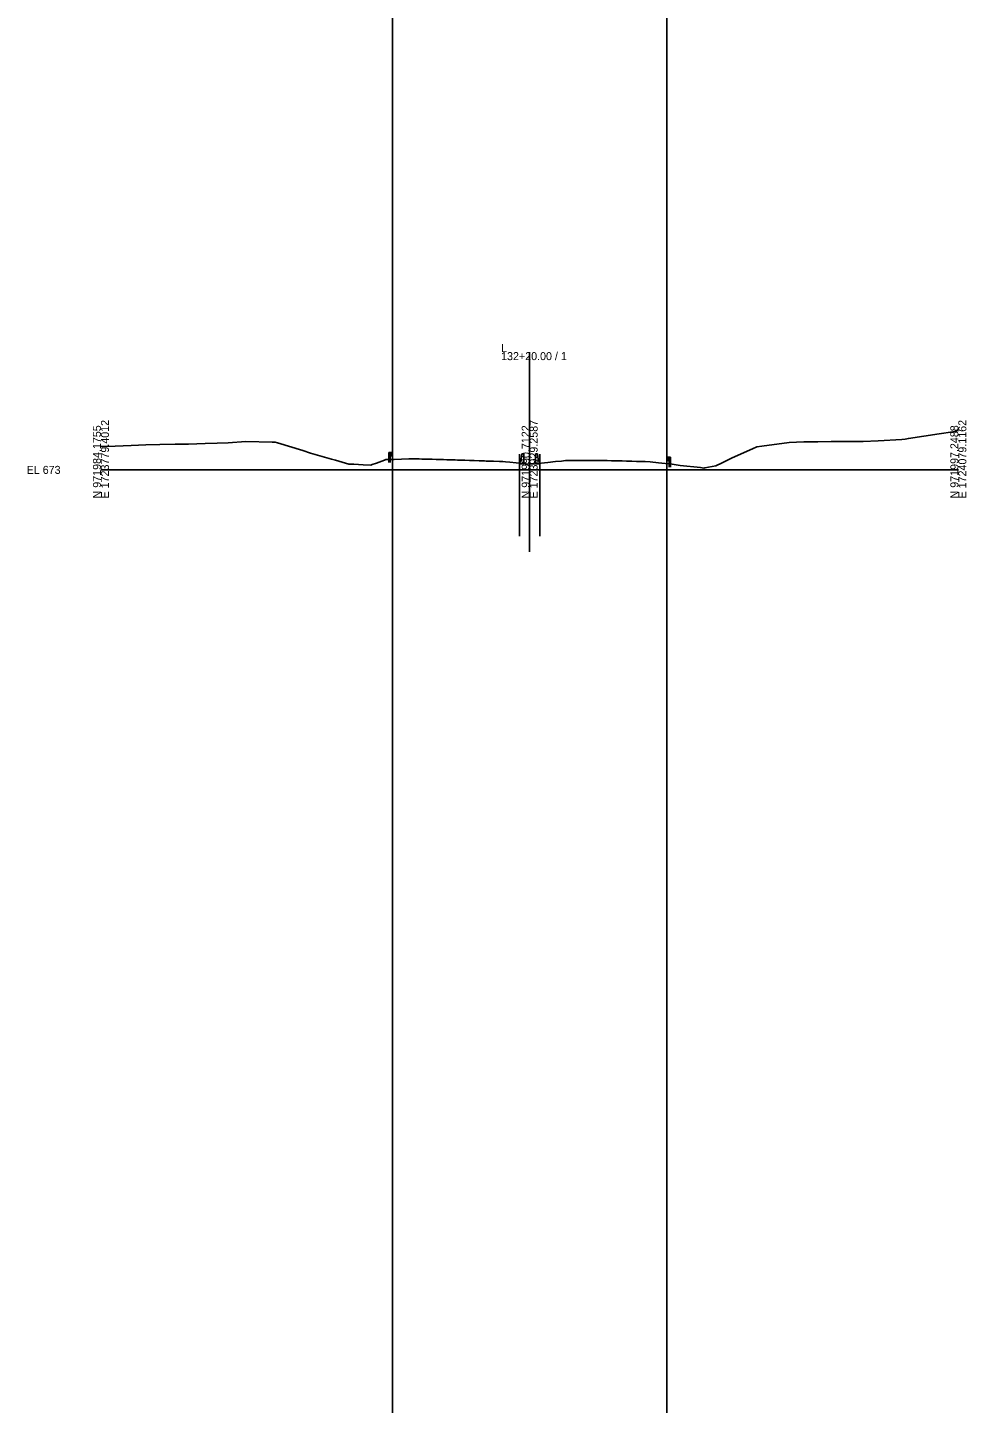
# Model space of a CAD drawing. Extents: x -26 to 303, y -29 to 15026.
# Drawn here: x -25.7 to 302.8, y 11173.3 to 11654.8 of the extents above; entities that cross this region are included whole.
import ezdxf

# ---------------------------------------------------------------- set-up
doc = ezdxf.new("R2010")
doc.units = 0
for name, color, linetype in [('Exist Cross Section Cell', 7, 'Continuous'), ('Exist XS Center Line Elevation Label', 7, 'Continuous'), ('Exist XS Ground Line', 7, 'Continuous'), ('Scratch_Level_0', 7, 'Continuous'), ('Typical Guardrail CELL', 7, 'Continuous'), ('Typical Median Barrier CELL', 7, 'Continuous')]:
    doc.layers.add(name, color=color, linetype=linetype)

msp = doc.modelspace()

# ---------------------------------------------------------------- linework, layer by layer
at = {"layer": 'Exist Cross Section Cell'}
for p, q in [((150, 11500), (150, 11541.21)), ((0, 11500), (150, 11500)), ((150, 11500), (300, 11500))]:
    msp.add_line(p, q, dxfattribs=at)
at = {"layer": 'Exist XS Ground Line'}
msp.add_lwpolyline([(0, 11508.17), (0.61, 11508.2), (5.01, 11508.29), (10.62, 11508.5), (15.76, 11508.73), (20.63, 11508.83), (25.95, 11508.98), (30.64, 11508.96), (36.41, 11509.19), (40.65, 11509.36), (44.53, 11509.52), (50.66, 11509.95), (59.94, 11509.7), (60.98, 11509.71), (61.75, 11509.45), (70.68, 11506.75), (73.3, 11505.88), (80.68, 11503.75), (82.05, 11503.36), (86.68, 11502.02), (88.53, 11501.99), (91.73, 11501.77), (94.45, 11501.67), (94.95, 11501.87), (96.4, 11502.4), (99.22, 11503.44), (99.66, 11503.6), (100.74, 11503.64), (102.55, 11503.69), (107.68, 11503.85), (108.2, 11503.84), (109.83, 11503.82), (111.37, 11503.82), (112.33, 11503.79), (113.3, 11503.77), (114.82, 11503.72), (115.91, 11503.71), (117.32, 11503.69), (118.62, 11503.64), (119.81, 11503.6), (121.01, 11503.57), (122.3, 11503.53), (122.78, 11503.52), (123.1, 11503.51), (123.89, 11503.48), (124.79, 11503.45), (126.33, 11503.4), (127.29, 11503.37), (128.96, 11503.32), (129.8, 11503.29), (130.57, 11503.27), (132.32, 11503.2), (134.2, 11503.12), (134.81, 11503.09), (135.12, 11503.08), (135.68, 11503.07), (136.84, 11503.02), (137.31, 11503), (139.39, 11502.93), (139.8, 11502.91), (140.66, 11502.89), (141.5, 11502.86), (143.11, 11502.69), (147.49, 11502.24), (150.13, 11501.97), (151.76, 11502.14), (156.4, 11502.6), (159.09, 11502.9), (161.17, 11503.11), (162.55, 11503.24), (162.88, 11503.23), (163.5, 11503.24), (164.22, 11503.27), (164.52, 11503.27), (164.87, 11503.27), (165.61, 11503.27), (167.35, 11503.27), (168.97, 11503.28), (169.86, 11503.29), (170.82, 11503.29), (172.38, 11503.29), (173.48, 11503.29), (174.86, 11503.29), (176.1, 11503.27), (177.07, 11503.26), (178.68, 11503.21), (179.85, 11503.17), (180.94, 11503.15), (182.35, 11503.12), (183.89, 11503.08), (184.85, 11503.05), (185.72, 11503.03), (187.37, 11502.98), (188.7, 11502.95), (189.33, 11502.93), (189.86, 11502.9), (190.38, 11502.88), (192.19, 11502.8), (195.05, 11502.47), (199.85, 11501.95), (202.61, 11501.54), (209.81, 11500.78), (210.93, 11500.65), (211.29, 11500.74), (215.09, 11501.44), (217.33, 11502.48), (220.81, 11504.18), (227.92, 11507.35), (229.46, 11508.08), (231.22, 11508.31), (240.83, 11509.57), (245.94, 11509.81), (250.84, 11509.78), (255.53, 11509.92), (260.85, 11509.95), (266.65, 11509.93), (271.89, 11510.2), (280.18, 11510.62), (281.35, 11510.79), (282.52, 11511), (293.34, 11512.58), (298.05, 11513.33), (300, 11513.74)], dxfattribs=at)
at = {"layer": 'Scratch_Level_0'}
for p, q in [((102, 15009.56), (102, -28.7)), ((198, 15009.56), (198, -28.7)), ((146.46, 11505.5), (146.46, 11476.8)), ((153.54, 11505.5), (153.54, 11476.8)), ((150, 11500), (150, 11471.3)), ((150, 11500), (150, 11471.3))]:
    msp.add_line(p, q, dxfattribs=at)
at = {"layer": 'Typical Guardrail CELL'}
for p, q in [((101.18, 11506.12), (100.68, 11506.12)), ((100.68, 11506.12), (100.68, 11503.63)), ((101.18, 11506.12), (101.18, 11503.63)), ((101.18, 11506.12), (101.68, 11506.12)), ((101.18, 11504.96), (101.68, 11504.96)), ((101.68, 11506.12), (101.68, 11504.96)), ((101.68, 11506.12), (101.97, 11505.92)), ((101.68, 11505.59), (101.97, 11505.79)), ((101.68, 11505.54), (101.68, 11505.59)), ((101.68, 11505.54), (101.68, 11505.49)), ((101.68, 11505.49), (101.97, 11505.29)), ((101.68, 11504.96), (101.97, 11505.16)), ((101.18, 11503.63), (100.68, 11503.63)), ((100.68, 11503.63), (100.68, 11502.63)), ((101.18, 11503.63), (101.18, 11502.63)), ((198.32, 11504.49), (198.03, 11504.29)), ((198.32, 11503.96), (198.03, 11504.16)), ((198.32, 11503.86), (198.03, 11503.66)), ((198.32, 11503.33), (198.03, 11503.53)), ((198.82, 11504.49), (198.32, 11504.49)), ((198.32, 11504.49), (198.32, 11503.33)), ((198.32, 11503.91), (198.32, 11503.96)), ((198.32, 11503.91), (198.32, 11503.86)), ((198.82, 11503.33), (198.32, 11503.33)), ((198.82, 11504.49), (198.82, 11502.01)), ((198.82, 11504.49), (199.32, 11504.49)), ((198.82, 11502.01), (199.32, 11502.01)), ((198.82, 11502.01), (198.82, 11501)), ((199.32, 11504.49), (199.32, 11502.01)), ((199.32, 11502.01), (199.32, 11501))]:
    msp.add_line(p, q, dxfattribs=at)
for centre, start, end in [((101.92, 11505.85), 304.9888, 54.997), ((101.92, 11505.23), 304.9634, 54.9941), ((198.08, 11504.22), 125.003, 235.0112), ((198.08, 11503.6), 125.0059, 235.0366)]:
    msp.add_arc(centre, 0.0776, start, end, dxfattribs=at)
at = {"layer": 'Typical Median Barrier CELL'}
for p, q in [((147.07, 11503.6), (147.29, 11505.56)), ((147.29, 11505.56), (147.96, 11505.56)), ((147.96, 11505.56), (147.96, 11502.14)), ((152.71, 11505.56), (152.04, 11505.56)), ((152.04, 11505.56), (152.04, 11502.14)), ((152.93, 11503.6), (152.71, 11505.56)), ((146.46, 11502.56), (146.92, 11503.21)), ((146.46, 11502.14), (146.46, 11502.56)), ((147.96, 11502.14), (146.46, 11502.14)), ((152.04, 11502.14), (153.54, 11502.14)), ((153.54, 11502.56), (153.08, 11503.21)), ((153.54, 11502.14), (153.54, 11502.56))]:
    msp.add_line(p, q, dxfattribs=at)
for centre, start, end in [((146.24, 11503.69), 325.0039, 353.9447), ((153.76, 11503.69), 186.0553, 214.9961)]:
    msp.add_arc(centre, 0.833, start, end, dxfattribs=at)

# ---------------------------------------------------------------- texts
at = {"layer": 'Exist Cross Section Cell'}
for s, p in [('L', (140, 11541.21)), ('132+20.00 / 1', (140, 11538.41)), ('EL 673', (-26, 11498.6))]:
    msp.add_text(s, height=2.8, dxfattribs=at).set_placement(p)
for s, p in [('N 971984.1755', (0, 11490)), ('E 1723779.4012', (2.8, 11490)), ('N 971990.7122', (150, 11490)), ('E 1723929.2587', (152.8, 11490)), ('N 971997.2488', (300, 11490)), ('E 1724079.1162', (302.8, 11490))]:
    msp.add_text(s, height=2.8, rotation=90, dxfattribs=at).set_placement(p)
at = {"layer": 'Exist XS Center Line Elevation Label'}
msp.add_text('674.98', height=0.18, dxfattribs=at).set_placement((149.62, 11501.49))

doc.saveas('drawing.dxf')
